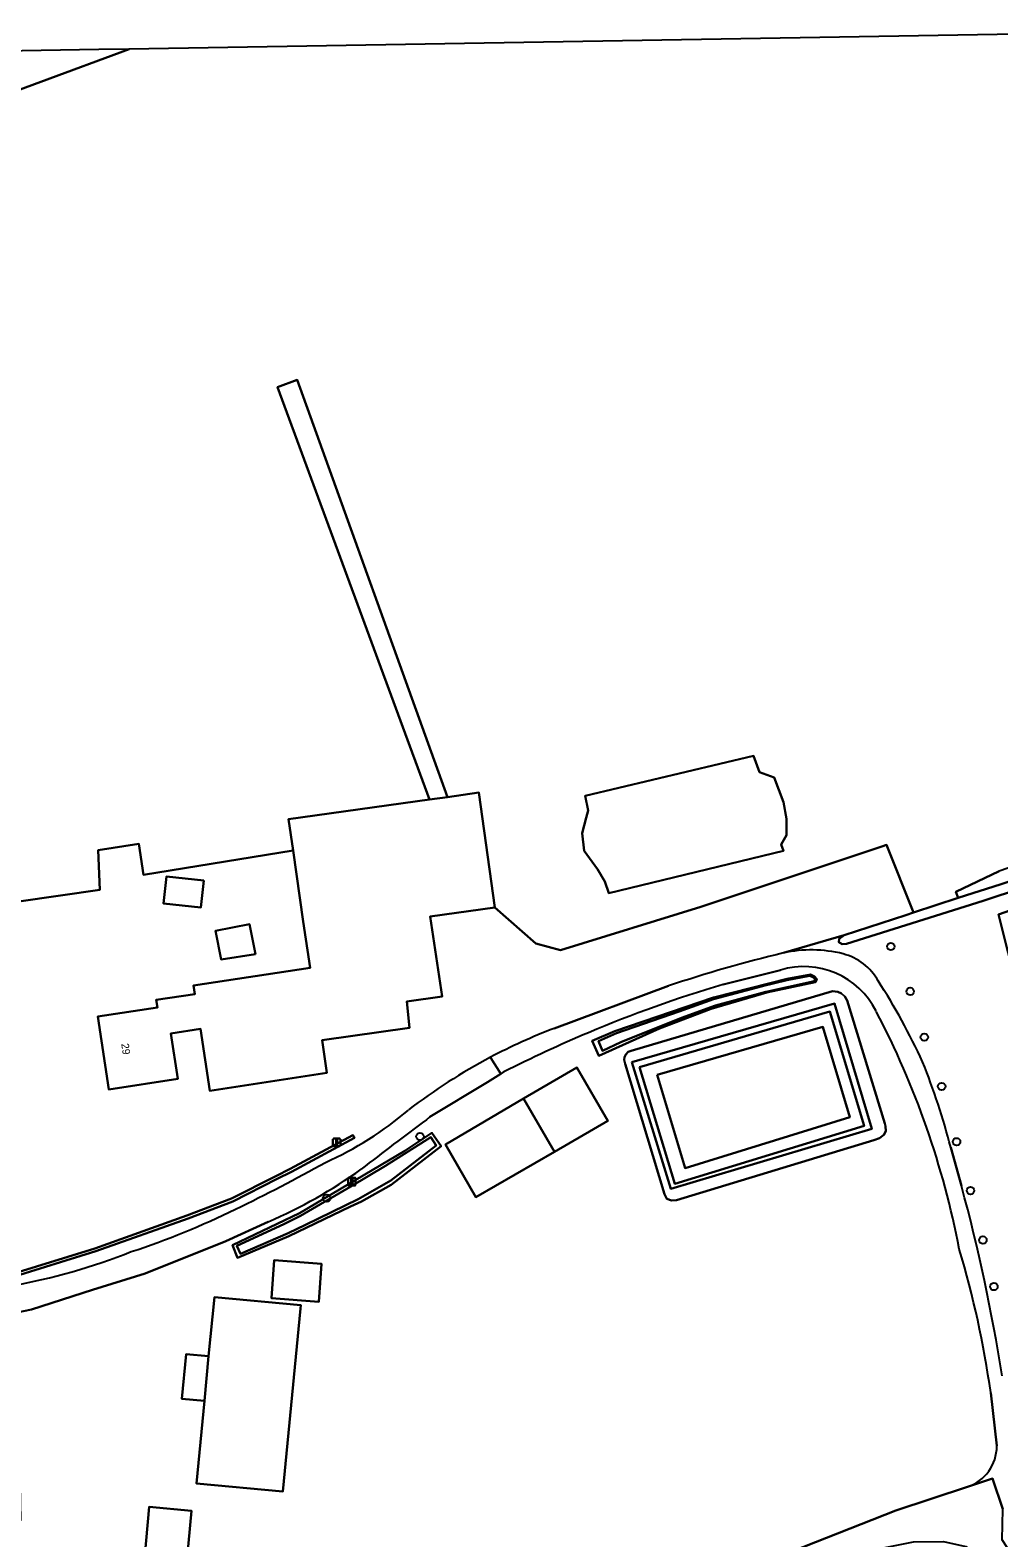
# Model space of a CAD drawing. Extents: x 162510 to 163918, y 388494 to 389774.
# Drawn here: x 162674.3 to 162801.7, y 389562 to 389760.2 of the extents above; entities that cross this region are included whole.
import ezdxf

# ---------------------------------------------------------------- set-up
doc = ezdxf.new("R2010")
doc.units = 0
for name, color, linetype in [('IMGEO_Boom', 7, 'Continuous'), ('IMGEO_Erf', 7, 'Continuous'), ('IMGEO_Grasland_agrarisch', 7, 'Continuous'), ('IMGEO_Grasland_overig', 7, 'Continuous'), ('IMGEO_Groenvoorziening', 7, 'Continuous'), ('IMGEO_Haag', 7, 'Continuous'), ('IMGEO_Houtwal', 7, 'Continuous'), ('IMGEO_Lichtmast', 7, 'Continuous'), ('IMGEO_Oever', 7, 'Continuous'), ('IMGEO_Open_loods', 7, 'Continuous'), ('IMGEO_Pand', 7, 'Continuous'), ('IMGEO_Pand_nummerreeks', 7, 'Continuous'), ('IMGEO_Rijbaan_lokaal_onverhard', 7, 'Continuous'), ('IMGEO_Rijbaan_lokaal_open', 7, 'Continuous'), ('IMGEO_Waterloop', 7, 'Continuous')]:
    doc.layers.add(name, color=color, linetype=linetype)

msp = doc.modelspace()

# ---------------------------------------------------------------- linework, layer by layer
at = {"layer": 'IMGEO_Boom'}
for centre in [(162787.45, 389639.73), (162790, 389633.82), (162791.85, 389627.8), (162794.13, 389621.32), (162725.52, 389614.73), (162796.1, 389614.05), (162797.93, 389607.62), (162713.25, 389606.62), (162799.56, 389601.12), (162801.01, 389595)]:
    msp.add_circle(centre, 0.489, dxfattribs=at)
at = {"layer": 'IMGEO_Erf'}
for points in [[(162687.28, 389757.73), (162683.29, 389757.67), (162640.34, 389756.94), (162639.37, 389756.93), (162639.38, 389756.91), (162643.42, 389750), (162647.64, 389742.8), (162649.79, 389743.64), (162652.36, 389744.85)], [(162697.08, 389648.4), (162696.69, 389644.85), (162691.81, 389645.38), (162692.2, 389648.93)], [(162703.89, 389638.7), (162699.38, 389638.02), (162698.64, 389641.79), (162703.11, 389642.66)], [(162748.16, 389627.32), (162751.16, 389628.57), (162764.14, 389633), (162773.77, 389635.47), (162776.88, 389636.02), (162777.41, 389635.79), (162777.71, 389635.41), (162777.53, 389635.03), (162771.15, 389633.66), (162763.8, 389631.53), (162757.03, 389628.95), (162749.05, 389625.35)], [(162752.49, 389624.29), (162752.39, 389624.8), (162752.44, 389625.15), (162752.61, 389625.53), (162752.89, 389625.86), (162753.29, 389626.01), (162779.77, 389633.84), (162780.5, 389633.74), (162780.97, 389633.52), (162781.41, 389633.16), (162781.69, 389632.64), (162786.66, 389616.45), (162786.75, 389616.1), (162786.77, 389615.45), (162786.52, 389614.95), (162785.98, 389614.53), (162785.22, 389614.26), (162759.25, 389606.35), (162758.61, 389606.3), (162757.98, 389606.55), (162757.67, 389607.16)], [(162732.87, 389606.78), (162728.87, 389613.69), (162739.13, 389619.73), (162746.14, 389623.8), (162750.25, 389616.79), (162743.22, 389612.74)], [(162716.4, 389605.53), (162708.26, 389601.65), (162701.52, 389598.78), (162700.85, 389600.44), (162709.68, 389604.64), (162723.55, 389612.84), (162727.1, 389615.21), (162728.3, 389613.48), (162721.73, 389608.4), (162717.83, 389606.21)], [(162705.98, 389593.47), (162706.36, 389598.47), (162712.58, 389597.99), (162712.2, 389592.99)], [(162707.49, 389568.04), (162696.13, 389569.12), (162697.17, 389579.98), (162694.21, 389580.26), (162694.77, 389586.13), (162697.73, 389585.85), (162698.48, 389593.62), (162709.84, 389592.54), (162709.8, 389592.12)], [(162694.09, 389550.39), (162683.64, 389551.34), (162684.47, 389559.61), (162689.28, 389559.14), (162689.91, 389566.03), (162695.48, 389565.52)]]:
    msp.add_lwpolyline(points, close=True, dxfattribs=at)
for points in [[(162735.37, 389644.85), (162726.88, 389643.65), (162728.46, 389633.15), (162723.78, 389632.5), (162724.15, 389629.02), (162712.66, 389627.4), (162713.27, 389623.09), (162697.9, 389620.76), (162696.67, 389628.89), (162692.75, 389628.29), (162693.66, 389622.3), (162684.59, 389620.93), (162683.14, 389630.5), (162690.98, 389631.68), (162690.82, 389632.71), (162695.89, 389633.47), (162695.72, 389634.6), (162711.09, 389636.92), (162710.17, 389643.03), (162708.84, 389652.34), (162689.14, 389649.13), (162688.55, 389653.24), (162683.2, 389652.4), (162683.4, 389647.17), (162672.75, 389645.66)], [(162773.32, 389638.87), (162781.32, 389641.23), (162789.4, 389643.86), (162790.43, 389644.2), (162786.88, 389653.1), (162786.25, 389652.88), (162762.48, 389644.96), (162744.01, 389639.23), (162740.78, 389640.1), (162735.37, 389644.85)], [(162772.93, 389636.61), (162765.38, 389634.74)], [(162665.43, 389634.67), (162665.5, 389630.94), (162665.78, 389629.1), (162667.72, 389616.27), (162671.53, 389596.53), (162682.77, 389600.02), (162694.88, 389604.33), (162700.74, 389606.57), (162706.58, 389609.52), (162708.45, 389610.47), (162716.7, 389614.9), (162716.89, 389614.55), (162708.64, 389610.11), (162706.76, 389609.16), (162700.9, 389606.2), (162695.02, 389603.96), (162682.9, 389599.64), (162671.61, 389596.13), (162671.64, 389595.96), (162671.78, 389595.09)], [(162743.17, 389628.94), (162758.19, 389634.53)], [(162736.57, 389623.23), (162736.15, 389622.97), (162734.4, 389621.87), (162726.83, 389617.33), (162726.37, 389616.92)], [(162705.55, 389603.52), (162699.99, 389600.99), (162689.36, 389596.71), (162682.45, 389594.59), (162674.43, 389591.99), (162672.34, 389591.57), (162672.54, 389590.33), (162672.73, 389578.64), (162672.97, 389564.25), (162672.43, 389564.22), (162672.4, 389563.04), (162672.36, 389560.9), (162672.33, 389559.41), (162672.17, 389551.86), (162669.89, 389530.14), (162669.39, 389520.32), (162669.24, 389518.99), (162673.37, 389519.09)], [(162801.39, 389574.04), (162800.58, 389581.05)], [(162675.54, 389519.85), (162679.52, 389521.34), (162765.33, 389556.56), (162788.12, 389565.57), (162797.51, 389568.67), (162797.54, 389568.68)]]:
    msp.add_lwpolyline(points, dxfattribs=at)
for centre, radius, start, end in [((162816.79, 389458.84), 185.21, 103.5769, 108.445), ((162776.03, 389626.48), 10.6, 26.4271, 107.0473), ((162814.11, 389470.9), 170.92, 106.5625, 112.8702), ((162685.25, 389578.6), 113.23, 10.853, 27.6763), ((162770.23, 389558.09), 75.85, 110.9, 117.8602), ((162814.2, 389470.61), 171.23, 112.8624, 116.9629), ((162771.61, 389555.96), 78.38, 118.0273, 127.3996), ((162694.84, 389652.34), 44.89, 293.9708, 310.5304), ((162891.88, 389389.6), 281.19, 126.0578, 128.2489), ((162604.48, 389805.88), 222.82, 295.7482, 299.1694), ((162679.38, 389664.22), 66.1, 293.3237, 305.5321), ((162654.73, 389699.79), 105.43, 288.142, 296.1938), ((162657.31, 389675.46), 81.66, 280.2033, 291.7402), ((162675.11, 389563.51), 126.69, 7.9603, 16.7021), ((162795.74, 389574.03), 5.65, 288.5666, 0.0028)]:
    msp.add_arc(centre, radius, start, end, dxfattribs=at)
at = {"layer": 'IMGEO_Grasland_agrarisch'}
for points in [[(162835.2, 389760.22), (162687.28, 389757.73), (162652.36, 389744.85)], [(162672.75, 389645.66), (162683.4, 389647.17), (162683.2, 389652.4), (162688.55, 389653.24), (162689.14, 389649.13), (162708.84, 389652.34), (162708.25, 389656.46), (162726.79, 389659.05), (162706.78, 389713.29), (162709.36, 389714.24), (162729.16, 389659.38), (162733.26, 389659.96), (162735.37, 389644.85), (162740.78, 389640.1), (162744.01, 389639.23), (162762.48, 389644.96), (162786.25, 389652.88), (162786.88, 389653.1), (162790.43, 389644.2), (162796.31, 389646.11), (162795.99, 389646.9), (162801.7, 389649.65)], [(162809.57, 389646.73), (162801.62, 389643.91), (162810.38, 389609.16)]]:
    msp.add_lwpolyline(points, dxfattribs=at)
msp.add_lwpolyline([(162769.38, 389664.81), (162770.19, 389662.64), (162772.09, 389661.96), (162773.32, 389658.7), (162773.72, 389656.53), (162773.72, 389654.36), (162773.04, 389653.13), (162773.32, 389652.32), (162750.37, 389646.75), (162749.83, 389648.25), (162748.88, 389649.88), (162747.11, 389652.32), (162746.84, 389654.63), (162747.38, 389656.66), (162747.65, 389657.61), (162747.24, 389659.52)], close=True, dxfattribs=at)
at = {"layer": 'IMGEO_Grasland_overig'}
for points in [[(162747.24, 389659.52), (162747.65, 389657.61), (162747.38, 389656.66), (162746.84, 389654.63), (162747.11, 389652.32), (162748.88, 389649.88), (162749.83, 389648.25), (162750.37, 389646.75), (162773.32, 389652.32), (162773.04, 389653.13), (162773.72, 389654.36), (162773.72, 389656.53), (162773.32, 389658.7), (162772.09, 389661.96), (162770.19, 389662.64), (162769.38, 389664.81)], [(162801.7, 389649.65), (162795.99, 389646.9), (162796.31, 389646.11), (162801.94, 389647.94), (162807.12, 389649.63), (162813.96, 389652.08), (162816.79, 389653.57), (162818.86, 389656.13), (162819.37, 389657.45), (162818.06, 389657.85), (162817.6, 389655.14)]]:
    msp.add_lwpolyline(points, close=True, dxfattribs=at)
for points in [[(162810.06, 389649.21), (162799.61, 389645.72), (162781.6, 389640.09), (162781.06, 389640.01), (162780.63, 389640.3), (162780.66, 389640.73), (162781.32, 389641.23)], [(162810.38, 389609.16), (162801.62, 389643.91), (162809.57, 389646.73)], [(162781.32, 389641.23), (162773.32, 389638.87)], [(162765.38, 389634.74), (162772.93, 389636.61)], [(162758.19, 389634.53), (162743.17, 389628.94)], [(162734.79, 389625.14), (162736.15, 389622.97), (162736.57, 389623.23)], [(162796.74, 389608.23), (162795.32, 389613.31)], [(162795.32, 389613.31), (162796.74, 389608.23)], [(162800.58, 389581.05), (162801.39, 389574.04)], [(162797.54, 389568.68), (162800.82, 389569.76), (162802.2, 389565.73)]]:
    msp.add_lwpolyline(points, dxfattribs=at)
for centre, radius, start, end in [((162776.99, 389621.93), 17.34, 76.0835, 102.2521), ((162776.99, 389621.93), 17.34, 76.0835, 102.2521), ((162816.79, 389458.84), 185.21, 103.5769, 108.445), ((162776.03, 389626.48), 10.6, 26.4271, 107.0473), ((162779.37, 389631.63), 7.34, 29.1353, 75.8332), ((162779.37, 389631.63), 7.34, 29.1353, 75.8332), ((162715.16, 389589.52), 84.11, 24.6095, 32.9031), ((162715.16, 389589.52), 84.11, 24.6095, 32.9031), ((162814.11, 389470.9), 170.92, 106.5625, 112.8702), ((162685.25, 389578.6), 113.23, 10.853, 27.6763), ((162770.23, 389558.09), 75.85, 110.9, 117.8602), ((162814.2, 389470.61), 171.23, 112.8624, 116.9629), ((162704.65, 389589.76), 93.68, 14.5608, 21.7973), ((162704.65, 389589.76), 93.68, 14.5608, 21.7973), ((162566.49, 389545.95), 238.53, 9.002, 15.1352), ((162566.49, 389545.95), 238.53, 9.002, 15.1352), ((162675.11, 389563.51), 126.69, 7.9603, 16.7021), ((162795.74, 389574.03), 5.65, 288.5666, 0.0028)]:
    msp.add_arc(centre, radius, start, end, dxfattribs=at)
at = {"layer": 'IMGEO_Groenvoorziening'}
msp.add_lwpolyline([(162716.7, 389614.9), (162708.45, 389610.47), (162706.58, 389609.52), (162700.74, 389606.57), (162694.88, 389604.33), (162682.77, 389600.02), (162671.53, 389596.53), (162671.61, 389596.13), (162682.9, 389599.64), (162695.02, 389603.96), (162700.9, 389606.2), (162706.76, 389609.16), (162708.64, 389610.11), (162716.89, 389614.55)], close=True, dxfattribs=at)
at = {"layer": 'IMGEO_Haag'}
msp.add_lwpolyline([(162716.7, 389614.9), (162708.45, 389610.47), (162706.58, 389609.52), (162700.74, 389606.57), (162694.88, 389604.33), (162682.77, 389600.02), (162671.53, 389596.53), (162671.61, 389596.13), (162682.9, 389599.64), (162695.02, 389603.96), (162700.9, 389606.2), (162706.76, 389609.16), (162708.64, 389610.11), (162716.89, 389614.55)], close=True, dxfattribs=at)
at = {"layer": 'IMGEO_Houtwal'}
msp.add_lwpolyline([(162726.79, 389659.05), (162729.16, 389659.38), (162709.36, 389714.24), (162706.78, 389713.29)], close=True, dxfattribs=at)
at = {"layer": 'IMGEO_Lichtmast'}
for p, q in [((162714.07, 389613.57), (162714.07, 389614.37)), ((162714.07, 389614.37), (162714.07, 389613.57)), ((162714.17, 389614.47), (162714.96, 389614.47)), ((162714.96, 389614.47), (162714.17, 389614.47)), ((162714.96, 389613.47), (162714.17, 389613.47)), ((162714.17, 389613.47), (162714.96, 389613.47)), ((162715.06, 389614.37), (162715.06, 389613.57)), ((162715.06, 389613.57), (162715.06, 389614.37)), ((162716.16, 389609.31), (162716.95, 389609.31)), ((162716.95, 389609.31), (162716.16, 389609.31)), ((162716.06, 389608.41), (162716.06, 389609.21)), ((162716.06, 389609.21), (162716.06, 389608.41)), ((162716.95, 389608.31), (162716.16, 389608.31)), ((162716.16, 389608.31), (162716.95, 389608.31)), ((162717.05, 389609.21), (162717.05, 389608.41)), ((162717.05, 389608.41), (162717.05, 389609.21))]:
    msp.add_line(p, q, dxfattribs=at)
for points in [[(162714.49, 389614.35), (162714.64, 389614.35), (162714.64, 389613.6), (162714.49, 389613.6), (162714.49, 389614.35)], [(162716.48, 389609.18), (162716.63, 389609.18), (162716.63, 389608.43), (162716.48, 389608.43), (162716.48, 389609.18)]]:
    msp.add_lwpolyline(points, dxfattribs=at)
for centre, start, end in [((162714.17, 389614.37), 90, 180), ((162714.17, 389614.37), 90, 180), ((162714.17, 389613.57), 180, 270), ((162714.17, 389613.57), 180, 270), ((162714.96, 389614.37), 0, 90), ((162714.96, 389614.37), 360, 90), ((162714.96, 389613.57), 270, 0), ((162714.96, 389613.57), 270, 0), ((162716.16, 389609.21), 90, 180), ((162716.16, 389609.21), 90, 180), ((162716.95, 389609.21), 0, 90), ((162716.95, 389609.21), 360, 90), ((162716.16, 389608.41), 180, 270), ((162716.16, 389608.41), 180, 270), ((162716.95, 389608.41), 270, 0), ((162716.95, 389608.41), 270, 0)]:
    msp.add_arc(centre, 0.1, start, end, dxfattribs=at)
at = {"layer": 'IMGEO_Oever'}
for points in [[(162763.8, 389631.53), (162771.15, 389633.66), (162777.53, 389635.03), (162777.71, 389635.41), (162777.41, 389635.79), (162776.88, 389636.02), (162773.77, 389635.47), (162764.14, 389633), (162751.16, 389628.57), (162748.16, 389627.32), (162749.05, 389625.35), (162757.03, 389628.95)], [(162759.62, 389631.19), (162764.14, 389632.81), (162770.59, 389634.49), (162773.82, 389635.31), (162776.81, 389635.85), (162777.2, 389635.68), (162777.48, 389635.4), (162777.38, 389635.16), (162774.01, 389634.44), (162771.03, 389633.76), (162764.4, 389631.96), (162759.92, 389630.35), (162751.93, 389627.13), (162749.52, 389626.02), (162748.98, 389627.26), (162751.37, 389628.31)], [(162781.69, 389632.64), (162781.41, 389633.16), (162780.97, 389633.52), (162780.5, 389633.74), (162779.77, 389633.84), (162753.29, 389626.01), (162752.89, 389625.86), (162752.61, 389625.53), (162752.44, 389625.15), (162752.39, 389624.8), (162752.49, 389624.29), (162757.67, 389607.16), (162757.98, 389606.55), (162758.61, 389606.3), (162759.25, 389606.35), (162785.22, 389614.26), (162785.98, 389614.53), (162786.52, 389614.95), (162786.77, 389615.45), (162786.75, 389616.1), (162786.66, 389616.45)], [(162753.4, 389624.52), (162780.05, 389632.21), (162784.94, 389615.73), (162758.53, 389607.85)], [(162753.4, 389624.52), (162758.53, 389607.85), (162784.94, 389615.73), (162780.05, 389632.21)], [(162754.39, 389623.84), (162759.06, 389608.53), (162783.96, 389616.15), (162779.41, 389631.17)], [(162754.39, 389623.84), (162779.41, 389631.17), (162783.96, 389616.15), (162759.06, 389608.53)], [(162756.72, 389622.84), (162778.49, 389629.17), (162782.04, 389617.27), (162760.39, 389610.59)], [(162716.4, 389605.53), (162717.83, 389606.21), (162721.73, 389608.4), (162728.3, 389613.48), (162727.1, 389615.21), (162723.55, 389612.84), (162709.68, 389604.64), (162700.85, 389600.44), (162701.52, 389598.78), (162708.26, 389601.65)], [(162701.92, 389599.3), (162701.45, 389600.37), (162707.61, 389603.22), (162709.83, 389604.3), (162716.43, 389608.15), (162720.97, 389610.87), (162726.95, 389614.67), (162727.67, 389613.54), (162721.68, 389608.97), (162717.41, 389606.49), (162710.46, 389603.11), (162708.18, 389602.01)]]:
    msp.add_lwpolyline(points, close=True, dxfattribs=at)
at = {"layer": 'IMGEO_Open_loods'}
msp.add_lwpolyline([(162739.13, 389619.73), (162728.87, 389613.69), (162732.87, 389606.78), (162743.22, 389612.74)], close=True, dxfattribs=at)
at = {"layer": 'IMGEO_Pand'}
for points in [[(162726.88, 389643.65), (162735.37, 389644.85), (162733.26, 389659.96), (162729.16, 389659.38), (162726.79, 389659.05), (162708.25, 389656.46), (162708.84, 389652.34), (162710.17, 389643.03), (162711.09, 389636.92), (162695.72, 389634.6), (162695.89, 389633.47), (162690.82, 389632.71), (162690.98, 389631.68), (162683.14, 389630.5), (162684.59, 389620.93), (162693.66, 389622.3), (162692.75, 389628.29), (162696.67, 389628.89), (162697.9, 389620.76), (162713.27, 389623.09), (162712.66, 389627.4), (162724.15, 389629.02), (162723.78, 389632.5), (162728.46, 389633.15)], [(162697.08, 389648.4), (162692.2, 389648.93), (162691.81, 389645.38), (162696.69, 389644.85)], [(162703.89, 389638.7), (162703.11, 389642.66), (162698.64, 389641.79), (162699.38, 389638.02)], [(162743.22, 389612.74), (162750.25, 389616.79), (162746.14, 389623.8), (162739.13, 389619.73)], [(162712.58, 389597.99), (162706.36, 389598.47), (162705.98, 389593.47), (162712.2, 389592.99)], [(162709.8, 389592.12), (162709.84, 389592.54), (162698.48, 389593.62), (162697.73, 389585.85), (162697.17, 389579.98), (162696.13, 389569.12), (162707.49, 389568.04)], [(162697.73, 389585.85), (162694.77, 389586.13), (162694.21, 389580.26), (162697.17, 389579.98)], [(162689.28, 389559.14), (162684.47, 389559.61), (162683.64, 389551.34), (162694.09, 389550.39), (162695.48, 389565.52), (162689.91, 389566.03)]]:
    msp.add_lwpolyline(points, close=True, dxfattribs=at)
at = {"layer": 'IMGEO_Rijbaan_lokaal_onverhard'}
msp.add_lwpolyline([(162749.68, 389547.35), (162758.46, 389550.93), (162759.86, 389551.5), (162762.7, 389552.48), (162768.52, 389554.18), (162781.93, 389559.73), (162790.45, 389561.45), (162794.38, 389561.5), (162797.3, 389560.83), (162798.23, 389560.18), (162799.84, 389559.06), (162802.98, 389552.67), (162805.1, 389552.99), (162802.74, 389560.7), (162802.08, 389561.71), (162802.2, 389565.73), (162800.82, 389569.76), (162797.54, 389568.68), (162797.51, 389568.67), (162788.12, 389565.57), (162765.33, 389556.56), (162679.52, 389521.34), (162675.54, 389519.85)], dxfattribs=at)
at = {"layer": 'IMGEO_Rijbaan_lokaal_open'}
for points in [[(162726.37, 389616.92), (162726.83, 389617.33), (162734.4, 389621.87), (162736.15, 389622.97), (162734.79, 389625.14)], [(162699.99, 389600.99), (162705.55, 389603.52)], [(162664.46, 389587.51), (162666.83, 389587.61), (162666.99, 389589.58), (162667.93, 389590.68), (162672.34, 389591.57), (162674.43, 389591.99), (162682.45, 389594.59), (162689.36, 389596.71), (162699.99, 389600.99)]]:
    msp.add_lwpolyline(points, dxfattribs=at)
for centre, radius, start, end in [((162771.61, 389555.96), 78.38, 118.0273, 127.3996), ((162694.84, 389652.34), 44.89, 293.9708, 310.5304), ((162891.88, 389389.6), 281.19, 126.0578, 128.2489), ((162604.48, 389805.88), 222.82, 295.7482, 299.1694), ((162679.38, 389664.22), 66.1, 293.3237, 305.5321), ((162654.73, 389699.79), 105.43, 288.142, 296.1938), ((162657.31, 389675.46), 81.66, 280.2033, 291.7402)]:
    msp.add_arc(centre, radius, start, end, dxfattribs=at)
at = {"layer": 'IMGEO_Waterloop'}
for points in [[(162789.4, 389643.86), (162781.32, 389641.23), (162780.66, 389640.73), (162780.63, 389640.3), (162781.06, 389640.01), (162781.6, 389640.09), (162799.61, 389645.72), (162810.06, 389649.21), (162814.72, 389650.91), (162818.18, 389652.52), (162820.1, 389654.62), (162821.12, 389656.85), (162820.25, 389657.18), (162819.37, 389657.45), (162818.86, 389656.13), (162816.79, 389653.57), (162813.96, 389652.08), (162807.12, 389649.63), (162801.94, 389647.94), (162796.31, 389646.11), (162790.43, 389644.2)], [(162764.4, 389631.96), (162771.03, 389633.76), (162774.01, 389634.44), (162777.38, 389635.16), (162777.48, 389635.4), (162777.2, 389635.68), (162776.81, 389635.85), (162773.82, 389635.31), (162770.59, 389634.49), (162764.14, 389632.81), (162759.62, 389631.19), (162751.37, 389628.31), (162748.98, 389627.26), (162749.52, 389626.02), (162751.93, 389627.13), (162759.92, 389630.35)], [(162756.72, 389622.84), (162760.39, 389610.59), (162782.04, 389617.27), (162778.49, 389629.17)], [(162727.67, 389613.54), (162726.95, 389614.67), (162720.97, 389610.87), (162716.43, 389608.15), (162709.83, 389604.3), (162707.61, 389603.22), (162701.45, 389600.37), (162701.92, 389599.3), (162708.18, 389602.01), (162710.46, 389603.11), (162717.41, 389606.49), (162721.68, 389608.97)]]:
    msp.add_lwpolyline(points, close=True, dxfattribs=at)

# ---------------------------------------------------------------- texts
at = {"layer": 'IMGEO_Pand_nummerreeks'}
msp.add_text('29', height=1, rotation=278.5773, dxfattribs=at).set_placement((162686.23, 389626.91))

doc.saveas('drawing.dxf')
